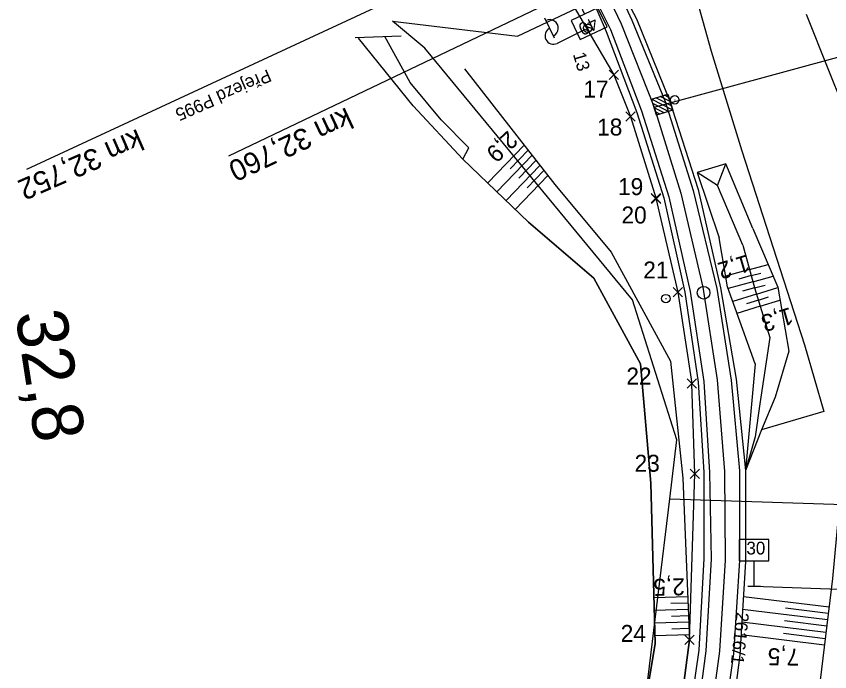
# Model space of a CAD drawing. Extents: x -804166 to -803706, y -1151030 to -1150147.
# Drawn here: x -803941 to -803845.1, y -1150593.1 to -1150515.9 of the extents above; entities that cross this region are included whole.
import ezdxf

# ---------------------------------------------------------------- set-up
doc = ezdxf.new("R2010")
doc.units = 0
for name, color, linetype in [('0381KM032-037P - Vrstva 1', 7, 'Continuous'), ('0381KM032-037P - Vrstva 16', 7, 'Continuous'), ('0381KM032-037P - Vrstva 25', 7, 'Continuous'), ('0381KM032-037P - Vrstva 27', 7, 'Continuous'), ('0381KM032-037P - Vrstva 3', 7, 'Continuous'), ('0381KM032-037P - Vrstva 4', 7, 'Continuous'), ('0381KM032-037P - Vrstva 48', 7, 'Continuous'), ('0381KM032-037P - Vrstva 49', 7, 'Continuous'), ('0381KM032-037P - Vrstva 5', 7, 'Continuous'), ('0381KM032-037P - Vrstva 50', 7, 'Continuous'), ('0381KM032-037P - Vrstva 55', 7, 'Continuous'), ('0381KM032-037P - Vrstva 57', 7, 'Continuous'), ('0381KM032-037P - Vrstva 7', 7, 'Continuous'), ('Default', 7, 'Continuous'), ('hran DP - hran DP', 7, 'Continuous'), ('PSR_C2_2_Lomove_body_Vimperk - Vrstva 60', 7, 'Continuous'), ('PSR_C2_2_trasa_Vimperk - Kabelová trasa', 7, 'Continuous')]:
    doc.layers.add(name, color=color, linetype=linetype)

msp = doc.modelspace()

# ---------------------------------------------------------------- linework, layer by layer
at = {"layer": '0381KM032-037P - Vrstva 1'}
for points in [[(-803874.069, -1150507.541), (-803869.666, -1150516.774), (-803865.801, -1150526.594), (-803862.645, -1150536.71)], [(-803862.645, -1150536.71), (-803860.057, -1150547.81), (-803858.364, -1150558.718), (-803857.51, -1150569.546), (-803857.425, -1150579.975), (-803858.096, -1150590.725), (-803859.58, -1150601.687), (-803861.73, -1150611.946), (-803864.691, -1150622.329), (-803868.306, -1150632.261), (-803873.118, -1150643.006), (-803878.784, -1150653.323), (-803884.455, -1150662.043), (-803890.68, -1150670.289), (-803894.474, -1150674.768)]]:
    msp.add_lwpolyline(points, dxfattribs=at)
at = {"layer": '0381KM032-037P - Vrstva 16'}
msp.add_line((-803901.044, -1150518.397), (-803895.63, -1150518.178), dxfattribs=at)
msp.add_lwpolyline([(-803888.331, -1150532.703), (-803887.637, -1150531.393), (-803890.889, -1150528.076), (-803894.531, -1150523.664), (-803897.525, -1150518.265)], dxfattribs=at)
at = {"layer": '0381KM032-037P - Vrstva 25'}
for p, q in [((-803877.522, -1150518.443), (-803878.676, -1150516.113)), ((-803873.129, -1150517.315), (-803874.036, -1150517.009)), ((-803874.075, -1150517.517), (-803877.211, -1150519.07)), ((-803873.284, -1150517.659), (-803874.117, -1150517.377))]:
    msp.add_line(p, q, dxfattribs=at)
msp.add_circle((-803873.627, -1150517.295), 0.5, dxfattribs=at)
msp.add_circle((-803873.627, -1150517.295), 0.5, dxfattribs=at)
for centre, start, end in [((-803878.088, -1150517.273), 295.64486, 117.05001), ((-803877.655, -1150518.174), 116.34744, 296.34744)]:
    msp.add_arc(centre, 1, start, end, dxfattribs=at)
at = {"layer": '0381KM032-037P - Vrstva 27'}
msp.add_line((-803863.381, -1150525.682), (-803863.351, -1150525.778), dxfattribs=at)
msp.add_circle((-803863.366, -1150525.73), 0.5, dxfattribs=at)
at = {"layer": '0381KM032-037P - Vrstva 3'}
for p, q in [((-803865.801, -1150526.594), (-803827.99, -1150516.298)), ((-803863.594, -1150526.953), (-803866.099, -1150525.639)), ((-803863.752, -1150526.447), (-803865.593, -1150525.482)), ((-803863.91, -1150525.94), (-803865.086, -1150525.323)), ((-803864.068, -1150525.434), (-803864.58, -1150525.166)), ((-803864.1, -1150527.111), (-803865.941, -1150526.145)), ((-803864.607, -1150527.269), (-803865.783, -1150526.652)), ((-803865.113, -1150527.427), (-803865.625, -1150527.158))]:
    msp.add_line(p, q, dxfattribs=at)
msp.add_lwpolyline([(-803865.503, -1150527.549), (-803866.099, -1150525.639), (-803864.19, -1150525.044), (-803863.594, -1150526.953)], close=True, dxfattribs=at)
at = {"layer": '0381KM032-037P - Vrstva 4'}
msp.add_line((-803875.88, -1150504.253), (-803939.777, -1150533.943), dxfattribs=at)
for points in [[(-803872.779, -1150506.875), (-803867.872, -1150516.171), (-803864.004, -1150525.679), (-803860.599, -1150536.286), (-803857.956, -1150547.888), (-803856.113, -1150558.65), (-803855.009, -1150569.422), (-803855.013, -1150580.14), (-803855.681, -1150591.137), (-803857.109, -1150602.102)], [(-803872.779, -1150506.875), (-803868.424, -1150516.34), (-803864.491, -1150525.922), (-803861.191, -1150536.397), (-803858.415, -1150547.949), (-803856.721, -1150558.765), (-803855.706, -1150569.464), (-803855.706, -1150580.041), (-803856.439, -1150591.045), (-803858.016, -1150602.009)], [(-803875.392, -1150508.511), (-803870.942, -1150517.43), (-803867.281, -1150527.019), (-803864.067, -1150537.143), (-803861.546, -1150548.304), (-803859.948, -1150558.943), (-803859.253, -1150569.653), (-803859.085, -1150579.867)], [(-803875.392, -1150508.511), (-803871.454, -1150517.68), (-803867.834, -1150527.236), (-803864.663, -1150537.291), (-803862.152, -1150548.382), (-803860.595, -1150558.999), (-803859.922, -1150569.628), (-803859.947, -1150579.801), (-803860.5, -1150590.58), (-803862.041, -1150601.171)], [(-803859.085, -1150579.867), (-803859.701, -1150590.693), (-803861.107, -1150601.386)]]:
    msp.add_lwpolyline(points, dxfattribs=at)
at = {"layer": '0381KM032-037P - Vrstva 48'}
for p, q in [((-803881.117, -1150531.067), (-803885.404, -1150535.52)), ((-803880.652, -1150531.665), (-803882.757, -1150533.853)), ((-803880.186, -1150532.262), (-803884.323, -1150536.561)), ((-803879.255, -1150533.458), (-803883.242, -1150537.601)), ((-803879.721, -1150532.86), (-803881.751, -1150534.97)), ((-803878.789, -1150534.056), (-803880.745, -1150536.088)), ((-803878.324, -1150534.653), (-803882.161, -1150538.641)), ((-803854.539, -1150545.729), (-803857.362, -1150546.5)), ((-803854.539, -1150545.729), (-803852.357, -1150545.132)), ((-803854.341, -1150546.452), (-803855.79, -1150546.848)), ((-803854.341, -1150546.452), (-803853.202, -1150546.141)), ((-803854.144, -1150547.176), (-803851.767, -1150546.526)), ((-803854.144, -1150547.176), (-803857.074, -1150547.977)), ((-803853.946, -1150547.899), (-803855.383, -1150548.292)), ((-803853.946, -1150547.899), (-803852.709, -1150547.561)), ((-803853.726, -1150548.616), (-803851.216, -1150547.835)), ((-803853.726, -1150548.616), (-803856.53, -1150549.489)), ((-803853.503, -1150549.332), (-803854.89, -1150549.764)), ((-803853.503, -1150549.332), (-803852.294, -1150548.956)), ((-803853.28, -1150550.048), (-803850.955, -1150549.325)), ((-803853.28, -1150550.048), (-803856.023, -1150550.902)), ((-803861.839, -1150584.311), (-803865.814, -1150584.417)), ((-803845.169, -1150585.523), (-803855.266, -1150584.307)), ((-803861.809, -1150585.06), (-803863.801, -1150585.114)), ((-803861.779, -1150585.81), (-803865.774, -1150585.917)), ((-803845.348, -1150587.012), (-803855.357, -1150585.806)), ((-803845.259, -1150586.267), (-803850.285, -1150585.662)), ((-803861.749, -1150586.559), (-803863.751, -1150586.613)), ((-803845.438, -1150587.757), (-803850.42, -1150587.157)), ((-803861.719, -1150587.309), (-803865.734, -1150587.416)), ((-803861.688, -1150588.058), (-803863.701, -1150588.112)), ((-803845.528, -1150588.501), (-803855.448, -1150587.306)), ((-803861.658, -1150588.808), (-803865.694, -1150588.916)), ((-803845.707, -1150589.991), (-803855.539, -1150588.806)), ((-803845.617, -1150589.246), (-803850.556, -1150588.651))]:
    msp.add_line(p, q, dxfattribs=at)
at = {"layer": '0381KM032-037P - Vrstva 49'}
for p, q in [((-803858.306, -1150535.807), (-803857.356, -1150533.258)), ((-803853.881, -1150556.86), (-803855.009, -1150569.422)), ((-803853.877, -1150565.433), (-803855.009, -1150569.422))]:
    msp.add_line(p, q, dxfattribs=at)
for points in [[(-803866.91, -1150495.141), (-803866.848, -1150501.095), (-803862.336, -1150508.281), (-803859.067, -1150519.976)], [(-803859.067, -1150519.976), (-803855.447, -1150531.748), (-803848.057, -1150554.624), (-803845.788, -1150562.48), (-803853.14, -1150564.614), (-803855.009, -1150569.422)], [(-803888.13, -1150522.065), (-803877.502, -1150535.708), (-803870.854, -1150543.675), (-803863.849, -1150556.524), (-803862.399, -1150570.315), (-803861.636, -1150589.369), (-803863.02, -1150600.178)], [(-803888.331, -1150532.703), (-803880.592, -1150540.151), (-803872.905, -1150546.743), (-803867.412, -1150556.856), (-803866.176, -1150570.896), (-803865.67, -1150589.811), (-803867.321, -1150599.808), (-803870.937, -1150611.902)], [(-803854.155, -1150540.878), (-803857.356, -1150533.258), (-803860.708, -1150534.282), (-803858.11, -1150541.981)], [(-803855.323, -1150542.862), (-803858.306, -1150535.807), (-803860.708, -1150534.282)], [(-803854.155, -1150540.878), (-803851.218, -1150547.825), (-803849.897, -1150555.364)], [(-803853.881, -1150556.86), (-803857.154, -1150547.754), (-803858.11, -1150541.981)], [(-803855.323, -1150542.862), (-803853.921, -1150547.99), (-803852.134, -1150553.731)], [(-803852.134, -1150553.731), (-803853.332, -1150561.547), (-803853.877, -1150565.433)], [(-803849.897, -1150555.364), (-803851.515, -1150560.763), (-803853.14, -1150564.614)], [(-803838.825, -1150566.88), (-803844.043, -1150574.496), (-803844.762, -1150582.145), (-803846.556, -1150597.039), (-803847.173, -1150599.748), (-803857.384, -1150629.008)], [(-803855.009, -1150569.422), (-803855.013, -1150580.14), (-803855.681, -1150591.137), (-803857.109, -1150602.102), (-803859.611, -1150612.518), (-803862.49, -1150623.34), (-803866.1, -1150633.182), (-803870.873, -1150644.181), (-803876.806, -1150654.687), (-803882.51, -1150663.405)]]:
    msp.add_lwpolyline(points, dxfattribs=at)
at = {"layer": '0381KM032-037P - Vrstva 5'}
for p, q in [((-803875.265, -1150512.897), (-803915.956, -1150532.369)), ((-803854.751, -1150583.067), (-803853.251, -1150583.067)), ((-803854.001, -1150583.067), (-803809.398, -1150584.605))]:
    msp.add_line(p, q, dxfattribs=at)
for points in [[(-803875.265, -1150512.897), (-803873.991, -1150515.613), (-803875.575, -1150516.356), (-803874.513, -1150518.62), (-803871.345, -1150517.133), (-803872.407, -1150514.87), (-803873.991, -1150515.613)], [(-803854.001, -1150583.067), (-803854.001, -1150580.067), (-803852.251, -1150580.067), (-803852.251, -1150577.567), (-803855.751, -1150577.567), (-803855.751, -1150580.067), (-803854.001, -1150580.067)]]:
    msp.add_lwpolyline(points, dxfattribs=at)
at = {"layer": '0381KM032-037P - Vrstva 50'}
msp.add_lwpolyline([(-803870.937, -1150611.902), (-803867.321, -1150599.808), (-803865.67, -1150589.811), (-803866.176, -1150570.896), (-803867.412, -1150556.856), (-803872.905, -1150546.743), (-803880.592, -1150540.151), (-803888.331, -1150532.703), (-803894.19, -1150526.416), (-803900.653, -1150518.475)], dxfattribs=at)
at = {"layer": '0381KM032-037P - Vrstva 55'}
msp.add_line((-803863.95, -1150572.75), (-803843.4, -1150573.43), dxfattribs=at)
at = {"layer": '0381KM032-037P - Vrstva 7'}
msp.add_line((-803864.421, -1150549.114), (-803864.405, -1150549.212), dxfattribs=at)
for centre, radius in [((-803859.955, -1150548.467), 0.75), ((-803864.413, -1150549.163), 0.5)]:
    msp.add_circle(centre, radius, dxfattribs=at)
at = {"layer": 'hran DP - hran DP'}
for p, q in [((-803881.88, -1150518.24), (-803874.06, -1150514.53)), ((-803847.85, -1150515.64), (-803845.22, -1150522.21)), ((-803892.84, -1150519.63), (-803896.64, -1150516.44)), ((-803896.64, -1150516.44), (-803881.88, -1150518.24)), ((-803868.33, -1150549.32), (-803892.84, -1150519.63)), ((-803845.22, -1150522.21), (-803843.61, -1150526.23)), ((-803863.11, -1150565.8), (-803868.33, -1150549.32)), ((-803863.95, -1150572.75), (-803863.11, -1150565.8)), ((-803868.49, -1150610.44), (-803863.95, -1150572.75))]:
    msp.add_line(p, q, dxfattribs=at)
at = {"layer": 'PSR_C2_2_Lomove_body_Vimperk - Vrstva 60'}
for p, q in [((-803871.075, -1150523.333), (-803869.975, -1150522.233)), ((-803869.975, -1150523.333), (-803871.075, -1150522.233)), ((-803869.143, -1150528.243), (-803868.043, -1150527.143)), ((-803868.043, -1150528.243), (-803869.143, -1150527.143)), ((-803866.14, -1150537.865), (-803865.04, -1150536.765)), ((-803865.04, -1150537.865), (-803866.14, -1150536.765)), ((-803866.117, -1150537.941), (-803865.017, -1150536.841)), ((-803865.017, -1150537.941), (-803866.117, -1150536.841)), ((-803863.554, -1150548.931), (-803862.454, -1150547.831)), ((-803862.454, -1150548.931), (-803863.554, -1150547.831)), ((-803861.879, -1150559.728), (-803860.779, -1150558.628)), ((-803860.779, -1150559.728), (-803861.879, -1150558.628)), ((-803861.549, -1150570.371), (-803860.449, -1150569.271)), ((-803860.449, -1150570.371), (-803861.549, -1150569.271)), ((-803862.186, -1150589.919), (-803861.086, -1150588.819)), ((-803861.086, -1150589.919), (-803862.186, -1150588.819))]:
    msp.add_line(p, q, dxfattribs=at)
at = {"layer": 'PSR_C2_2_trasa_Vimperk - Kabelová trasa'}
for p, q in [((-803884.501, -1150499.004), (-803870.525, -1150522.783)), ((-803870.525, -1150522.783), (-803868.593, -1150527.693)), ((-803868.593, -1150527.693), (-803865.567, -1150537.391)), ((-803865.59, -1150537.315), (-803863.004, -1150548.381)), ((-803863.004, -1150548.381), (-803861.329, -1150559.178))]:
    msp.add_line(p, q, dxfattribs=at)
msp.add_lwpolyline([(-803868.21, -1150616.463), (-803863.02, -1150600.178), (-803861.636, -1150589.369), (-803860.999, -1150569.821), (-803861.329, -1150559.178)], dxfattribs=at)

# ---------------------------------------------------------------- texts
at = {"layer": '0381KM032-037P - Vrstva 25'}
msp.add_text('13', height=1.5, rotation=286.34744, dxfattribs=at).set_placement((-803875.377, -1150520.344))
at = {"layer": '0381KM032-037P - Vrstva 4'}
for s, height, p in [('Přejezd P995', 1.5, (-803911.348, -1150522.078)), ('km 32,752', 2.5, (-803926.702, -1150529.095))]:
    msp.add_text(s, height=height, rotation=203.59524, dxfattribs=at).set_placement(p)
at = {"layer": '0381KM032-037P - Vrstva 48'}
for s, rotation, p in [('2,9', 222.91886, (-803883.021, -1150529.264)), ('1,2', 196.35186, (-803854.887, -1150543.961)), ('1,3', 196.38012, (-803849.768, -1150550.152)), ('2,5', 181.53237, (-803862.191, -1150582.109)), ('7,5', 179.00475, (-803848.659, -1150590.424))]:
    msp.add_text(s, height=2, rotation=rotation, dxfattribs=at).set_placement(p)
at = {"layer": '0381KM032-037P - Vrstva 5'}
for s, height, p in [('40', 1.5, (-803872.846, -1150515.904)), ('km 32,760', 2.5, (-803902.064, -1150526.559))]:
    msp.add_text(s, height=height, rotation=205.13221, dxfattribs=at).set_placement(p)
msp.add_text('30', height=1.5, dxfattribs=at).set_placement((-803854.914, -1150579.317))
at = {"layer": '0381KM032-037P - Vrstva 57'}
msp.add_text('2616/1', height=1.5, rotation=263.79604, dxfattribs=at).set_placement((-803856.079, -1150586.074))
at = {"layer": '0381KM032-037P - Vrstva 7'}
msp.add_text('32,8', height=6, rotation=278.82233, dxfattribs=at).set_placement((-803941.117, -1150550.923))
at = {"layer": 'Default'}
for s, p in [('17', (-803874.134, -1150525.465)), ('18', (-803872.511, -1150529.932)), ('19', (-803870.046, -1150536.954)), ('20', (-803869.64, -1150540.302)), ('21', (-803867.07, -1150546.785)), ('22', (-803869.063, -1150559.287)), ('23', (-803868.093, -1150569.563)), ('24', (-803869.731, -1150589.622))]:
    msp.add_text(s, height=2, dxfattribs=at).set_placement(p)

doc.saveas('drawing.dxf')
